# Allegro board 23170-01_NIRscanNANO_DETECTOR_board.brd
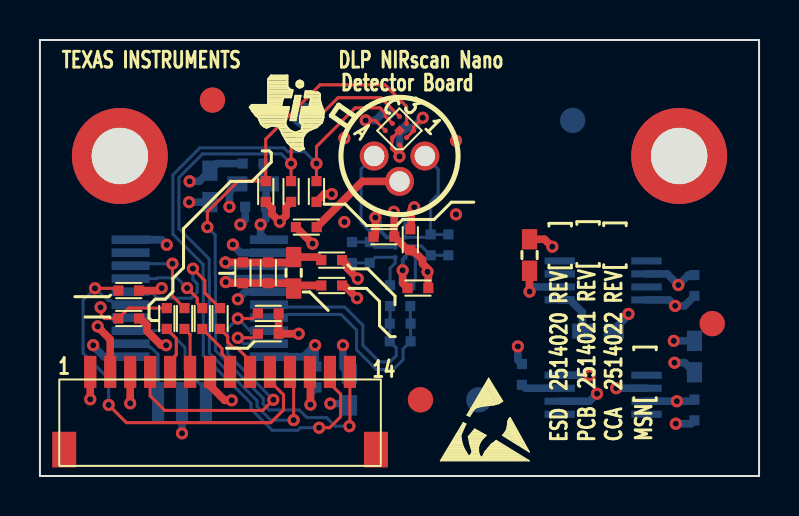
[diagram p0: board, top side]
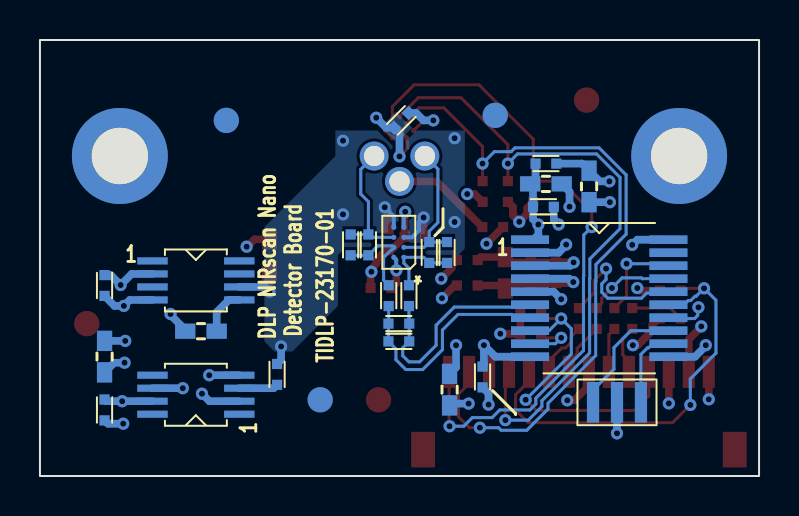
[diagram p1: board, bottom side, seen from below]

Outline 36 x 21.8 mm; copper layers: TOP, LY2VCC, LY3GND, BOTTOM. Coordinates in mm from the lower left corner of the outline.
Outline path: rectangle 0,0 36,21.8

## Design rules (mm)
net group PWR: nets N42023026 N42087581 N42087818 N42120494 N42163672

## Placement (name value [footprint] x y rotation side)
C1  -  [0402]  32.77 3.3 270 bottom
C2  -  [0402]  32.77 9.53 270 bottom
C3  -  [0603]  32.77 5.97 90 bottom
C4  -  [0603]  27.94 7.24 0 bottom
C5  -  [0603]  24.51 11.05 90 top
C6  -  [0603]  8.51 14.48 270 bottom
C7  -  [0603]  10.67 14.61 180 bottom
C8  -  [0402]  10.79 13.46 180 bottom
C9  -  [0402]  20.45 11.56 270 bottom
C10  -  [0603]  15.49 4.32 270 bottom
C11  -  [0402]  13.84 4.95 270 bottom
C12  -  [0402]  18.92 9.4 0 top
C13  -  [0402]  17.22 11.96 0 top
C14  -  [0402]  18.54 11.81 270 top
C15  -  [0402]  18.03 7.62 180 bottom
C16  -  [0402]  18.03 6.73 180 bottom
C17  -  [0402]  15.62 11.18 270 bottom
C18  -  [0402]  10.16 10.16 90 top
C19  -  [0402]  11.43 10.16 90 top
C20  -  [0603]  12.7 10.16 90 top
C21  -  [0402]  17.91 17.78 315 bottom
D1  -  [TO-18]  16.73 16 0 top
FB1  -  [0402]  10.67 15.62 180 bottom
J1  -  [CONN14-SM14B_JST]  9.02 5.21 0 top
NOREF  -  []  67.55 13.92 0 top
NOREF#2  -  [unnamed#2]  32 16 0 top
NOREF#3  -  []  0 0 90 top
NOREF#4  -  [unnamed#3]  33.66 7.62 0 top
NOREF#5  -  []  -19.05 -12.7 0 top
NOREF#6  -  [unnamed#2]  4 16 0 top
NOREF#7  -  []  44.45 31.75 0 top
NOREF#8  -  [unnamed#3]  8.64 18.8 0 top
NOREF#9  -  []  34.64 5.54 0 top
NOREF#10  -  []  0 0 90 top
NOREF#11  -  []  -19.05 31.75 0 top
NOREF#12  -  []  22.53 2.54 0 top
NOREF#13  -  []  -115.46 -53.59 0 top
NOREF#14  -  []  0 0 0 top
NOREF#15  -  [unnamed#3]  19.05 3.81 0 top
NOREF#16  -  []  11.87 17.92 0 top
NOREF#17  -  []  0 0 0 top
NOREF#18  -  [unnamed#3]  26.67 17.78 180 bottom
NOREF#19  -  [unnamed#3]  21.97 3.81 180 bottom
NOREF#20  -  [unnamed#3]  13.21 18.03 180 bottom
R1  -  [0402]  24.13 5.08 270 bottom
R2  -  [0402]  19.56 11.56 270 bottom
R3  -  [0402]  11.43 7.11 180 top
R4  -  [0402]  4.45 7.87 180 top
R5  -  [0402]  11.43 8.13 180 top
R6  -  [0402]  18.54 9.02 270 bottom
R7  -  [0402]  13.34 12.45 0 top
R8  -  [0402]  9.02 7.87 270 top
R9  -  [0402]  8.13 7.87 270 top
R10  -  [0402]  7.24 7.87 270 top
R11  -  [0402]  6.35 7.87 270 top
R12  -  [0402]  17.53 9.02 270 bottom
R13  -  [0402]  16.51 11.18 270 bottom
R14  -  [0402]  4.45 9.27 0 top
R15  -  [0402]  14.61 9.53 180 top
R16  -  [0402]  14.61 10.79 180 top
R17  -  [0402]  13.84 14.22 270 top
R18  -  [0402]  12.57 14.22 270 top
R19  -  [0402]  11.3 14.22 270 top
U1  -  [SOIC8-DGK_TI]  28.19 9.78 270 bottom
U2  -  [SOIC8-DGK_TI]  28.19 4.06 90 bottom
U3  -  [BGA8-YZD_TI]  18.03 11.68 0 bottom
U4  -  [SOIC20-DB_TI]  8 8.89 270 bottom
U5  -  [BGA8-YZF_TI]  18 17.27 135 top
Y1  -  [CRY3-CSTCE_MURATA]  7.11 3.68 180 bottom

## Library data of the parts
C1 C2 C8 C9 C11-C19 C21 FB1 R1-R19 = 0402: alternate symbols: (0402-1mm)
C3-C7 C10 C20 = 0603
D1 = TO-18
J1 = CONN14-SM14B_JST
U1 U2 = SOIC8-DGK_TI
U3 = BGA8-YZD_TI
U4 = SOIC20-DB_TI
U5 = BGA8-YZF_TI
Y1 = CRY3-CSTCE_MURATA

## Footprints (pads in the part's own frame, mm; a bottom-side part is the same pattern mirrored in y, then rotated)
0402
  rect 0.508x0.508 smd: 1(-0.521,0) 2(0.521,0)
0603
  rect 1.016x0.762 smd: 1(-0.787,0) 2(0.787,0)
BGA8-YZD_TI
  round 0.254 smd: A1(-0.25,0.75) A2(0.25,0.75) B1(-0.25,0.25) B2(0.25,0.25) C1(-0.25,-0.25) C2(0.25,-0.25) D1(-0.25,-0.75) D2(0.25,-0.75)
BGA8-YZF_TI
  round 0.254 smd: A1(-0.5,0.5) A2(0,0.5) A3(0.5,0.5) B1(-0.5,0) B3(0.5,0) C1(-0.5,-0.5) C2(0,-0.5) C3(0.5,-0.5)
CONN14-SM14B_JST
  rect 1.194x1.778 smd: (-7.8,-3.886) (7.8,-3.886)
  rect 0.61x1.6 smd: 1(-6.5,0) 2(-5.5,0) 3(-4.5,0) 4(-3.5,0) 5(-2.5,0) 6(-1.5,0) 7(-0.5,0) 8(0.5,0) 9(1.5,0) 10(2.5,0) 11(3.5,0) 12(4.5,0) 13(5.5,0) 14(6.5,0)
CRY3-CSTCE_MURATA
  rect 0.61x2.032 smd: 1(1.2,0) 2(0,0) 3(-1.2,0)
SOIC8-DGK_TI
  rect 0.356x1.524 smd: 1(-0.975,-2.173) 2(-0.325,-2.173) 3(0.325,-2.173) 4(0.975,-2.173) 5(0.975,2.173) 6(0.325,2.173) 7(-0.325,2.173) 8(-0.975,2.173)
SOIC20-DB_TI
  rect 0.432x1.905 smd: 1(-2.925,-3.464) 2(-2.275,-3.464) 3(-1.625,-3.464) 4(-0.975,-3.464) 5(-0.325,-3.464) 6(0.325,-3.464) 7(0.975,-3.464) 8(1.625,-3.464) 9(2.275,-3.464) 10(2.925,-3.464) 11(2.925,3.464) 12(2.275,3.464) 13(1.625,3.464) 14(0.975,3.464) 15(0.325,3.464) 16(-0.325,3.464) 17(-0.975,3.464) 18(-1.625,3.464) 19(-2.275,3.464) 20(-2.925,3.464)
TO-18
  round 1.448 hole 1.016: 1(0,0) 2(1.27,-1.27) 3(2.54,0)
unnamed#2
  round 4.801 hole 2.819: (0,0)
unnamed#3
  round 1.27 smd: 1(0,0)

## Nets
GND: C1.2 C2.2 C3.2 C4.2 C5.2 C6.2 C7.2 C8.2 C10.2 C11.2 C12.2 C13.2 C14.2 C21.2 J1.1 J1.7 J1.12 R7.1 R14.2 R16.1 U1.4 U2.4 U3.D1 U4.2 U4.5 U4.11 U4.20 U5.A1 U5.A2 U5.B1 U5.C1 Y1.2
V2P5VREF: C5.1 C13.1 C14.1 R1.1 U1.6 U3.C1 U3.D2
V2P5VREFBUF: C3.1 R15.1 U2.2 U2.6
V3P3V: C10.1 C11.1 C21.1 J1.3 R3.1 R4.1 R5.1 R17.2 R18.2 R19.2 U4.10 U5.A3
V5P0V: C6.1 FB1.2 J1.2
V5P0VF: C1.1 C2.1 C7.1 C8.1 C12.1 FB1.1 U1.2 U2.7 U3.A2 U4.1
ANODE: C9.1 D1.3 R2.1 U3.C2
CATHODE: C17.1 D1.1 R13.1 U3.B1
CSZ: J1.5 R11.2
CSZ_S: R4.2 R11.1 U4.14
DIN: J1.8 R9.2
DIN_S: R9.1 U4.17
DOUT: R8.1 U4.16
DOUT_S: J1.9 R8.2
DRDYZ: J1.10 R14.1 U4.15
SCLK: J1.6 R10.2
SCLK_S: R10.1 U4.18
SYNCZ: J1.4 R5.2 U4.8
TDRDYZ: J1.14 R19.1 U5.C2
TSCL: J1.13 R17.1 U5.B3
TSDA: J1.11 R18.1 U5.C3
N41965449: C9.2 R2.2 R6.1 U3.B2
N41965551: C17.2 R12.1 R13.2 U3.A1
N41990102: C15.1 C16.1 R6.2 U4.7
N41990105: C15.2 C16.2 R12.2 U4.6
N42023026: C4.1 U1.5
N42087581: C18.1 C19.1 C20.1 R15.2 U4.4
N42087818: C18.2 C19.2 C20.2 R16.2 U4.3
N42088958: U4.12 Y1.1
N42090142: R3.2 U4.9
N42103947: U4.13 Y1.3
N42120494: R1.2 U2.3
N42163672: D1.2 R7.2

Pads without a net: NOREF#4 1; NOREF#8 1; NOREF#15 1; NOREF#18 1; NOREF#19 1; NOREF#20 1; U1 1 3 7 8; U2 1 5 8; U4 19

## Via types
v1: diameter 0.61, hole 0.305, TOP to BOTTOM, 68 vias

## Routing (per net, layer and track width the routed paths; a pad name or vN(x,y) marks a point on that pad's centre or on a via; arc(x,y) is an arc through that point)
GND: length 45.3
  TOP w0.152: U5.A1 18.08,16.48 18.08,16.06 v1(18,15.98) 17.62,16.36 17.62,16.72 17.64,16.74 17.64,16.91 U5.A2 18,17.27 ; U5.B1 U5.C1 18.71,17.46 v1(19.16,17.91)
  TOP w0.381: v1(17.71,13.21) 17.7,13.21 17.7,13.21 17.74,13.17 17.74,11.97 C13.2 18.41,11.29 C14.2 18.61,11.23 18.73,11.23 19.15,10.81 19.15,10.62 19.41,10.36 v1(19.41,10.21) 19.44,10.17 C12.2 ; J1.1 v1(2.52,3.84) ; v1(6.1,9.4) 5.97,9.27 R14.2 ; v1(9.6,3.78) 9.25,3.78 8.52,4.51 J1.7 ; v1(15.91,9.87) 15.38,10.4 15.38,10.54 R16.1 ; C5.2 25.26,11.84 25.65,11.44 v1(25.65,11.47) ; v1(13.54,3.57) 13.54,5.18 J1.12 ; R7.1 v1(13.65,11.61)
  LY2VCC w0.254: v1(19.16,17.91) 18.72,17.91 18.71,17.92
  LY3GND w0.254: v1(19.16,17.91) 19.16,18.94 19.18,18.95
  BOTTOM w0.203: U3.D1 17.78,13.14 v1(17.71,13.21)
  BOTTOM w0.381: v1(9.91,8.84) 9.91,8.83 10.29,9.22 U4.5 ; C7.2 9.49,14.21 v1(9.49,13.46) ; C10.2 15.4,3.62 v1(14.54,3.62) ; C4.2 28.73,7.32 29.46,8.05 v1(29.46,8.1) ; U4.20 6.09,11.82 v1(6.35,11.56) ; C11.2 13.54,4.13 v1(13.54,3.57) ; v1(18,15.98) 18,17.14 C21.2 18.66,17.41 v1(19.16,17.91) ; U4.2 10.03,11.17 9.65,11.55 9.65,11.57 v1(9.66,11.57) ; v1(31.83,2.61) 32.6,2.61 C1.2 ; U4.11 3.2,5.96 2.67,6.5 v1(2.67,6.54) ; U2.4 v1(27.53,5.04) ; C6.2 v1(7.47,13.69) ; Y1.2 v1(7.11,2.13) ; C3.2 v1(31.73,6.76) ; C8.2 10.27,12.81 v1(10.03,12.57) ; C2.2 32.27,8.51 v1(31.8,8.51) 31.5,8.8 U1.4
V2P5VREF: length 8.7
  TOP w0.381: C5.1 v1(24.51,9.22) ; v1(18.74,13.44) 18.58,13.28 18.58,12.37 C14.1 ; v1(16.79,12.92) 16.79,12.06 C13.1
  BOTTOM w0.203: v1(18.74,13.44) 18.28,12.98 U3.D2 ; U3.C1 17.37,11.93 17.03,12.28 17.03,12.72 16.81,12.94 16.81,12.92 v1(16.79,12.92)
  BOTTOM w0.381: U1.6 24.74,9.45 24.51,9.23 v1(24.51,9.22) ; R1.1 23.93,5.8 v1(23.93,6.48)
  vias: v1(15.24,16.89) v1(15.24,12.7) v1(20.83,16.76) v1(20.83,13.08)
V2P5VREFBUF: length 5.8
  TOP w0.381: v1(15.88,8.89) 15.24,9.53 R15.1
  BOTTOM w0.381: U2.2 27.51,3.74 v1(27.89,4.11) ; v1(31.76,5.66) 32.28,5.66 C3.1 ; U2.6 v1(28.85,4.39)
V3P3V: length 17.8
  TOP w0.152: U5.A3 16.78,17.78 v1(16.31,17.78)
  TOP w0.381: J1.3 v1(4.52,3.63) ; R4.1 5.03,7.87 5.36,7.55 5.36,7.25 6.05,6.55 6.29,6.55 6.32,6.53 v1(6.32,6.54) ; R5.1 R3.1 v1(12.95,7.11) ; v1(14.61,14.1) 14.24,14.1 R17.2 ; R19.2 11.61,13.39 11.61,13.1 v1(12,12.71) 12.32,13.02 12.32,13.46 12.56,13.7 R18.2
  LY2VCC w0.254: v1(16.31,17.78) 16.31,18.59
  BOTTOM w0.381: v1(16.31,17.78) 16.8,17.78 17.17,18.15 C21.1 ; v1(15.17,6.54) 15.17,5.43 C10.1 ; U4.10 13.2,5.96 v1(13.77,6.54) 13.77,5.54 C11.1
V5P0V: length 5.6
  TOP w0.381: J1.2 3.52,6.83 2.89,7.46 v1(2.89,7.48)
  BOTTOM w0.381: v1(7.49,14.73) 7.98,14.73 C6.1 8.86,15.62 FB1.2
V5P0VF: length 11.3
  TOP w0.381: v1(18.16,10.29) 18.16,9.64 C12.1
  BOTTOM w0.203: U3.A2 18.17,10.82 18.17,10.29 v1(18.16,10.29)
  BOTTOM w0.381: U2.7 v1(31.88,3.74) 32.68,3.74 C1.1 ; U1.2 31.41,10.1 v1(31.96,9.55) 32.46,10.05 C2.1 ; FB1.1 11.19,14.87 C7.1 11.32,14.47 C8.1 11.32,12.84 v1(11.05,12.57) 11.05,12.06 11.3,11.82 U4.1
ANODE: length 6.6
  BOTTOM w0.152: R2.1 19.41,11.93 U3.C2 ; R2.1 C9.1 ; R2.1 19.56,13.72 19.94,14.1 19.94,15.33 D1.3
CATHODE: length 7
  BOTTOM w0.152: D1.1 16.08,15.35 16.08,12.67 16.51,12.24 R13.1 ; R13.1 16.77,11.43 U3.B1 ; R13.1 C17.1
CSZ: length 2.5
  TOP w0.152: J1.5 6.6,5.29 6.6,5.84 6.83,6.06 6.83,6.88 R11.2
CSZ_S: length 5.9
  TOP w0.152: R11.1 4.45,8.39 R4.2 3.23,7.87 3.07,8.03 3.07,8.39 v1(3.03,8.43)
  BOTTOM w0.152: U4.14 4.5,7.87 3.23,7.87 3.07,8.03 3.07,8.39 v1(3.03,8.43)
DIN: length 2.7
  TOP w0.152: R9.2 9.11,6.37 9.11,6.11 9.52,5.7 J1.8
DIN_S: length 4.4
  TOP w0.152: v1(7.37,9.4) 7.87,8.89 7.87,8.65 R9.1
  BOTTOM w0.152: v1(7.37,9.4) 6.86,9.91 5.89,9.91 5.84,9.87 U4.17
DOUT: length 7.4
  TOP w0.152: R8.1 8.26,9.16 8.26,9.77 v1(7.66,10.37)
  BOTTOM w0.152: v1(7.66,10.37) 7.66,9.82 7.87,9.61 7.87,9.19 7.58,8.89 5.89,8.89 5.63,9.14 4.61,9.14 U4.16
DOUT_S: length 2.9
  TOP w0.152: J1.9 10.52,5.76 9.87,6.4 9.7,6.4 9.4,6.7 9.4,6.97 R8.2
DRDYZ: length 21.5
  TOP w0.152: v1(3.44,3.55) 4.33,2.67 11.56,2.67 12.19,3.3 12.19,4.06 11.52,4.74 J1.10 ; v1(2.75,9.38) 3.81,9.38 R14.1
  BOTTOM w0.152: U4.15 3.75,8.56 3.55,8.77 3.42,8.77 3.2,8.99 3.15,8.99 v1(2.75,9.38) 2.16,8.79 2.16,6.14 3.44,4.86 v1(3.44,3.55)
SCLK: length 2.3
  TOP w0.152: R10.2 7.52,7.08 J1.6
SCLK_S: length 4.6
  TOP w0.152: R10.1 6.63,9 v1(6.63,10.61)
  BOTTOM w0.152: v1(6.63,10.61) 4.64,10.61 U4.18
SYNCZ: length 16
  TOP w0.152: v1(11.68,3.81) 11.15,3.28 6.25,3.28 5.52,4.01 J1.4 ; v1(9.91,7.87) 10.66,7.87 R5.2
  BOTTOM w0.152: v1(11.68,3.81) 9.4,6.1 9.4,7.37 v1(9.91,7.87) 10.52,7.26 U4.8
TDRDYZ: length 33.4
  TOP w0.152: J1.14 15.52,2.56 15.49,2.54 v1(15.49,2.49) ; U5.C2 18.35,17.83 18.36,17.83 18.36,18.47 17.27,19.56 14.02,19.56 11.3,16.84 R19.1 9.92,14.74 8.38,13.21 v1(8.38,12.45)
  BOTTOM w0.152: v1(15.49,2.49) 14.78,2.49 14.35,2.92 13.36,2.92 12.98,3.3 11.47,3.3 11.18,3.6 11.18,3.89 8.79,6.27 8.79,9.99 8.78,10 8.78,12.05 v1(8.38,12.45)
TSCL: length 35.8
  TOP w0.152: J1.13 14.52,4.63 15.05,4.09 15.05,2.96 14.5,2.41 v1(13.98,2.41) ; U5.B3 17.27,18 17.27,18.16 17.03,18.41 15.78,18.41 13.84,16.47 v1(13.84,15.62) R17.1
  BOTTOM w0.152: v1(13.98,2.41) 13.04,2.41 12.91,2.29 11.63,2.29 10.57,3.35 10.57,3.63 8.18,6.02 8.18,9.73 8.17,9.75 8.17,10.58 6.65,12.09 6.65,15.05 8.01,16.41 12.22,16.41 12.41,16.22 13.25,16.22 v1(13.84,15.62)
TSDA: length 32.6
  TOP w0.152: J1.11 12.7,5.02 v1(12.7,2.79) ; U5.C3 17.06,18.91 14.92,18.91 12.57,16.56 v1(12.57,15.62) R18.1
  BOTTOM w0.152: v1(12.7,2.79) 11.55,2.79 10.87,3.47 10.87,3.76 8.48,6.15 8.48,9.86 8.47,9.87 8.47,10.85 6.96,12.37 6.96,14.93 8.13,16.1 12.09,16.1 v1(12.57,15.62)
N41965449: length 4.6
  BOTTOM w0.152: 18.31,11.43 18.39,11.51 19.08,11.51 R2.2 C9.2 ; 18.31,11.43 18.31,11.39 18.41,11.29 18.43,11.29 18.8,10.92 18.8,9.79 R6.1 ; 18.31,11.43 U3.B2
N41965551: length 3.8
  BOTTOM w0.152: R12.1 17.53,10.39 17.78,10.64 U3.A1 16.79,10.93 R13.2 C17.2
N41990102: length 11.5
  BOTTOM w0.152: U4.7 12.22,7.91 12.39,8.08 15.07,8.08 15.85,7.3 15.85,6.31 16.84,5.32 17.69,5.32 18.18,5.82 18.18,6.35 C16.1 C15.1 18.55,7.87 18.54,7.89 R6.2
N41990105: length 10.9
  BOTTOM w0.152: U4.6 11.58,8.45 15.26,8.45 16.17,7.54 16.17,6.54 17,5.71 17.53,5.71 17.84,6.02 17.84,6.41 C16.2 C15.2 17.51,7.87 17.53,7.89 R12.2
N42023026: length 2.3
  BOTTOM w0.381: U1.5 26.54,8.8 27.15,8.19 C4.1
N42087581: length 7.2
  TOP w0.381: v1(9.3,9.7) 9.33,9.7 9.33,9.64 C18.1 C19.1 12.43,9.64 C20.1 12.85,9.53 R15.2
  BOTTOM w0.381: v1(9.3,9.7) 9.33,9.7 9.5,9.87 U4.4
N42087818: length 7.2
  TOP w0.381: R16.2 13.93,10.95 C20.2 12.43,10.68 C19.2 C18.2 v1(9.28,10.68)
  BOTTOM w0.381: v1(9.28,10.68) 9.45,10.52 U4.3
N42088958: length 4
  BOTTOM w0.152: Y1.1 5.91,6.08 5.58,6.41 5.53,6.41 5.32,6.61 U4.12
N42090142: length 2.8
  TOP w0.152: v1(9.91,6.91) 10.71,6.91 R3.2
  BOTTOM w0.152: v1(9.91,6.91) 10.2,6.61 U4.9
N42103947: length 6.2
  BOTTOM w0.152: Y1.3 8.31,4.29 7.26,5.34 7.26,6.42 6.42,7.26 U4.13
N42120494: length 2
  BOTTOM w0.381: R1.2 24.3,4.39 U2.3
N42163672: length 5.1
  TOP w0.381: R7.2 16.14,14.73 D1.2

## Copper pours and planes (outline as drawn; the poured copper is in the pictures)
GND on LY2VCC (solid shape): 19.78,17.94 18.28,16.43 18.25,16.45 17.98,16.51 17.72,16.43 16.89,17.27 18.67,19.05
GND on BOTTOM: 18.93,17.46 18.17,18.22 17.36,17.41 18.12,16.65
GND on LY3GND: 35.11,0.89 0.89,0.89 0.89,20.91 35.11,20.91
GND on LY3GND: 18.8,17.58 18,18.38 17.19,17.58 18,16.78
V2P5VREF on BOTTOM: 14.73,17.27 14.73,11.37 15.07,11.03 17.51,11.03 17.71,11.22 20.91,11.22 21.08,11.05 21.08,8.51 23.37,6.22 24.26,6.22 24.77,6.73 24.77,12.45 21.21,16 21.21,17.27
V2P5VREF on LY3GND: 14.73,17.27 14.73,11.37 14.93,11.17 17.67,11.17 18.23,11.73 21.21,11.73 21.21,17.27
V2P5VREFBUF on LY2VCC: 15.62,9.27 25.91,9.27 28.83,6.35 31.88,6.35 32.38,5.84 32.38,5.21 31.88,4.7 31.24,4.7 31.11,4.57 31.11,3.17 29.84,1.91 17.53,1.91 16.89,2.54 16.89,6.6 15.24,8.26 15.24,8.89
V3P3V on LY2VCC: 16.18,17.12 15.95,17.12 15.11,16.28 15.11,13.26 13.92,12.06 12.06,12.06 11.68,12.45 11.68,13.21 11.51,13.39 10.87,13.39 8.89,11.4 8.89,9.27 9.53,8.64 10.79,8.64 11.18,8.26 14.35,8.26 16.13,6.48 16.13,2.54 15.49,1.91 2.03,1.91 0.89,3.05 0.89,19.56 1.91,20.57 16.59,20.57 17.7,19.46 17.7,18.64
V5P0V on LY2VCC: 4.78,7.34 4.6,7.16 0.89,7.16 0.89,19.56 1.91,20.57 8.38,20.57 8.38,15.14 4.78,11.53
V5P0VF on LY2VCC: 10.85,12.93 11.3,12.93 11.3,12.19 11.81,11.68 17.32,11.68 25.96,20.32 32.89,20.32 34.92,18.29 34.92,3.68 34.04,2.79 32.13,2.79 31.5,3.43 31.5,4.19 31.88,4.57 32.26,4.57 32.77,5.08 32.77,6.1 31.75,7.11 28.45,7.11 25.91,9.65 15.24,9.65 14.48,8.89 10.29,8.89 9.45,9.73 9.45,11.53

Small or netless copper shapes (teardrops, artwork), in the pictures only: 1 on TOP

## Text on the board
BOTTOM: LAYER 4 - SECONDARY SIDE | 4
Board Geometry/Soldermask Bottom: SOLDERMASK - SECONDARY SIDE | 6
Ref Des/Silkscreen Bottom: TIDLP-23170-01 | Detector Board | DLP NIRscan Nano | SILKSCREEN-SECONDARY SIDE | 8
TOP: LAYER 1 - PRIMARY SIDE | 1
Board Geometry/Soldermask Top: SOLDERMASK - PRIMARY SIDE | 5
Ref Des/Silkscreen Top: TEXAS INSTRUMENTS | DLP NIRscan Nano | Detector Board | ESD  2514020 REV[    ] | PCB  2514021 REV[    ] | CCA  2514022 REV[    ] | MSN[     ] | SILKSCREEN - PRIMARY SIDE | 7
LY2VCC: LAYER 2 - PWR PLANE | 2
LY3GND: LAYER 3 - GND PLANE | 3
DIMENSION: (OZ) | SOLDERPASTE - PRIMARY SIDE | RATING AND BE MARKED IN COPPER ON THE TOP SIDE OF THE | BOARD IN INDICATED AREA.(DETAIL A). | MATERIAL SHALL MEET A MINIMUM OF 94V-0 FLAMMABILITY | 9 | 11 | DIMENSION TOLERANCES ARE +/- 0.010". | DETAIL A(TOP) | LAYER 1 - PRIMARY SIDE - SIGNAL | LAYER 2 - POWER PLANE | LAYER 3 - GND PLANE | LAYER 4 - SECONDARY SIDE - SIGNAL | LAYER# | COPPER WEIGHT | HALF+PLATING | 1 | IMPEDANCE CONTROL | +/- 10% | 50ohm SINGLE ENDED | N/A | 75ohm SINGLE ENDED | 0 | PRIMARY SIDE VIEW | 100ohm DIFFERENTIAL | DRILL DRAWING | LAYER STACK-UP - ALL DIMENSIONS IN INCHES
PASTEMASK_BOTTOM: SOLDERPASTE - SECONDARY SIDE | 10
User.11: 19 | TOP SIDE VIA PLUG
User.18: ASSEMBLY
User.19: ASSEMBLY
User.22: 11 | Mobile Spectroscopy Det.Bd. | 2514021 | - | 30MAY2014 | TEXAS INSTRUMENTS
User.43: FIGURE | SIZE | 12.0 | 40.0 | 111.0 | DRILL CHART: TOP to BOTTOM | ALL UNITS ARE IN MILS | TOLERANCE | +3.0/-12.0 | +3.0/-3.0 | PLATED | QTY | 68 | 3 | 2
